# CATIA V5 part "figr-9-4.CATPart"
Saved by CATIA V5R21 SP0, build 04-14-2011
Part number: Part1
Bounding box of the stored display mesh (mm): x -71.324 to 69.61, y -139.735 to 0, z 0 to 45
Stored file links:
  D:\CATIA V5R21 E-RESOURCES\CATIA-V5R21\catia-v5r21-prt\c09-catia-v5r20-prt\c09-catia-v5r21-figr-9-4.CATPart
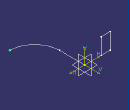
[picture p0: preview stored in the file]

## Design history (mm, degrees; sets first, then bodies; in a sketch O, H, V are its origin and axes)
Body1 (main body)
  Sketch1 on xy-plane, origin (0, 0, 0), H (1, 0, 0), V (0, 1, 0)
    line L1 (0, 0) -> (0, -70.1255)
    arc A1 centre (69.6095, -70.1255) radius 69.6095 from (0, -70.1255) to (69.6095, -139.7351) ccw
    vertical: L1 V
    tangency: A1 L1
  Sketch2 on zx-plane, origin (0, 0, 0), H (-1, 0, 0), V (0, 0, 1)
    point P1 (46.3244, 0)
    line L1 (46.3244, 0) -> (71.3244, 0)
    line L2 (71.3244, 0) -> (71.3244, 45)
    line L3 (71.3244, 45) -> (46.3244, 45)
    line L4 (46.3244, 45) -> (46.3244, 0)
    length L3 = 25
    length L2 = 45
    coincidence: P1 H
    horizontal: L1 H, L3 H
    vertical: L2 V, L4 V
  Rib1: profile Sketch2, centre curve Sketch1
